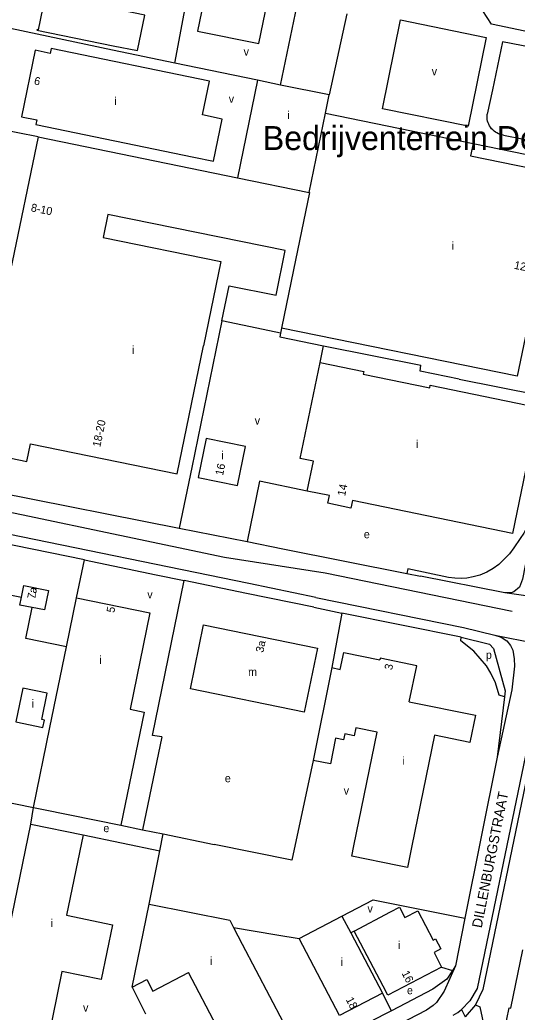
# Model space of a CAD drawing. Extents: x 157699 to 159683, y 381451 to 383293.
# Drawn here: x 158260 to 158508.3, y 381916.9 to 382412.9 of the extents above; entities that cross this region are included whole.
import ezdxf

# ---------------------------------------------------------------- set-up
doc = ezdxf.new("R2010")
doc.units = 0
for name, color, linetype in [('BLT_Basislijn', 7, 'Continuous'), ('BLT_Bebouwing', 7, 'Continuous'), ('BLT_Centroide', 7, 'Continuous'), ('BLT_Huisnummer', 7, 'Continuous'), ('BLT_Huisnummer_reeks', 7, 'Continuous'), ('BLT_Onderverdeling_panden', 7, 'Continuous'), ('BLT_Sport_parknaam', 7, 'Continuous'), ('BLT_Straatnaam', 7, 'Continuous'), ('BLT_Vlakafsluiter', 7, 'Continuous')]:
    doc.layers.add(name, color=color, linetype=linetype)

msp = doc.modelspace()

# ---------------------------------------------------------------- linework, layer by layer
at = {"layer": 'BLT_Basislijn'}
for p, q in [((158337.32, 382391.27), (158346.43, 382439.27)), ((158306.25, 382397.75), (158255.23, 382408.53)), ((158337.32, 382391.27), (158306.25, 382397.75)), ((158378.71, 382382.67), (158337.32, 382391.27)), ((158495.93, 382377.87), (158493.34, 382365.67)), ((158269.05, 382354.34), (158245.09, 382359.23)), ((158501.45, 382355.29), (158511.7, 382353.19)), ((158486.34, 382351.12), (158552.63, 382337.43)), ((158360.88, 382262.39), (158345.82, 382189.15)), ((158390.17, 382256.36), (158389.79, 382254.49)), ((158389.79, 382254.49), (158411.61, 382249.88)), ((158409.9, 382241.62), (158411.61, 382249.88)), ((158411.61, 382249.88), (158460.22, 382240.26)), ((158479.27, 382233.29), (158518.84, 382225.38)), ((158345.82, 382189.15), (158339.58, 382158.81)), ((158223.44, 382181.91), (158339.58, 382158.81)), ((158339.58, 382158.81), (158373.42, 382152.08)), ((158292.26, 382142.92), (158246.44, 382152.33)), ((158373.42, 382152.08), (158391.35, 382148.52)), ((158391.35, 382148.52), (158453.2, 382136.22)), ((158292.26, 382142.92), (158328.02, 382135.51)), ((158328.02, 382135.51), (158342.01, 382132.6)), ((158453.2, 382136.22), (158460.05, 382134.85)), ((158373.22, 382126.19), (158342.01, 382132.6)), ((158406.73, 382119.25), (158373.22, 382126.19)), ((158406.73, 382119.25), (158420.67, 382116.39)), ((158480.29, 382104.36), (158420.67, 382116.39)), ((158330.81, 382054.44), (158321.29, 382008.06)), ((158406.35, 382042.77), (158395.81, 381992.8)), ((158236.05, 382025.53), (158266.85, 382019.2)), ((158265.37, 382010.94), (158266.85, 382019.2)), ((158291.58, 382005.49), (158329.89, 381997.56)), ((158310.34, 382010.3), (158321.29, 382008.06)), ((158321.29, 382008.06), (158331.56, 382005.96)), ((158329.89, 381997.56), (158331.56, 382005.96)), ((158331.56, 382005.96), (158357.02, 382000.76)), ((158395.81, 381992.8), (158357.02, 382000.76)), ((158324.59, 381970.86), (158329.89, 381997.56)), ((158366.61, 381959.29), (158388.32, 381955.55)), ((158426.96, 381957.47), (158425.18, 381956.54)), ((158388.32, 381955.55), (158399.38, 381953.65)), ((158470.57, 381939.46), (158476, 381937.73)), ((158316.02, 381929.43), (158322.77, 381916.03)), ((158445.55, 381917.65), (158440.98, 381926.41)), ((158480.51, 381918.19), (158482.27, 381914.6))]:
    msp.add_line(p, q, dxfattribs=at)
for points in [[(158533.71, 382395.49), (158535.16, 382402.41), (158495.57, 382410.69), (158488.96, 382420.8), (158500.45, 382475.74)], [(158533.71, 382395.49), (158501.04, 382401.96), (158495.93, 382377.87)], [(158501.45, 382355.29), (158500.6, 382355.44), (158499.76, 382355.66), (158498.95, 382355.96), (158498.18, 382356.34), (158497.43, 382356.78), (158496.74, 382357.29), (158496.09, 382357.86), (158495.5, 382358.49), (158494.97, 382359.18), (158494.51, 382359.91), (158494.12, 382360.67), (158493.79, 382361.47), (158493.55, 382362.3), (158493.38, 382363.15), (158493.29, 382364.01), (158493.28, 382364.87), (158493.34, 382365.67)], [(158479.27, 382233.29), (158459.82, 382237.37), (158460.22, 382240.26)], [(158403.49, 382177.37), (158379.65, 382182.28), (158373.42, 382152.08)], [(158208.33, 382176.62), (158362.08, 382144.32), (158412.5, 382136.57), (158505.73, 382117.34)], [(158518.16, 382169.99), (158517.16, 382170.25), (158515.34, 382164.61), (158513.1, 382159.29), (158511.61, 382156.3), (158509.83, 382153.6), (158506.57, 382148.93), (158504.42, 382146.04), (158502, 382143.42), (158499.11, 382140.72), (158496.4, 382138.66), (158493.14, 382136.89), (158489.59, 382135.3), (158486.33, 382134.46), (158483.25, 382133.9), (158480.45, 382133.72), (158477.19, 382133.81), (158474.02, 382134.18), (158453.69, 382138.48), (158453.19, 382136.22)], [(158518.16, 382169.99), (158510.96, 382133.33), (158509.41, 382129.31), (158506.7, 382127.02), (158505.37, 382126.57), (158502.18, 382126.47)], [(158407.75, 382124.15), (158374.23, 382131.09), (158247.44, 382157.23)], [(158288.3, 382124.03), (158292.26, 382142.92)], [(158200.59, 382135.68), (158199.19, 382129.38), (158209.54, 382127.4), (158210.85, 382134.13), (158260.84, 382124.37)], [(158502.18, 382126.47), (158460.05, 382134.85)], [(158330.81, 382054.44), (158326.16, 382055.27), (158342.01, 382132.6)], [(158407.75, 382124.15), (158481.47, 382109.22), (158497.16, 382105.39)], [(158283.26, 382099.43), (158262.9, 382103.65), (158266.11, 382119.17)], [(158420.67, 382116.39), (158415.82, 382089.12)], [(158497.16, 382105.39), (158500.27, 382104.28), (158503.2, 382102.5), (158504.93, 382100.16), (158506.11, 382097.86)], [(158501.98, 382074.55), (158499.39, 382075.38), (158497.48, 382081.52), (158495.14, 382086.36), (158492.98, 382089.94), (158486.73, 382097.34), (158480.21, 382102.49), (158480.29, 382104.36)], [(158480.29, 382104.36), (158494.53, 382100.88), (158496.54, 382098.73), (158502.26, 382077.58), (158501.98, 382074.55)], [(158506.11, 382097.86), (158506.88, 382093.45), (158506.97, 382089.79), (158505.58, 382078.02), (158498.34, 382044.29)], [(158501.98, 382074.55), (158498.34, 382044.29), (158482.25, 381963.84)], [(158515.99, 382058.89), (158513.23, 382049.22), (158488.25, 381928.78)], [(158513.38, 382035.19), (158491.19, 381928.17), (158487.42, 381920.58)], [(158420.83, 381964.84), (158436.32, 381973.11), (158482.25, 381963.84)], [(158482.25, 381963.84), (158477.43, 381940.01)], [(158476, 381937.73), (158473.26, 381933.38), (158466.16, 381928.41), (158445.55, 381917.65)], [(158477.43, 381940.01), (158471.84, 381927.48), (158467.98, 381921.78), (158466.32, 381920.25), (158462.98, 381917.95), (158449.15, 381910.73)], [(158477.43, 381940.01), (158476, 381937.73)], [(158488.25, 381928.78), (158484.73, 381922.58), (158480.51, 381918.19)], [(158445.55, 381917.65), (158441.82, 381915.71), (158400.71, 381894.19)], [(158476.39, 381915.37), (158478.7, 381916.71), (158480.51, 381918.19)], [(158487.42, 381920.58), (158482.27, 381914.6)], [(158487.42, 381920.58), (158489.7, 381919.53), (158492.32, 381907.09), (158495.94, 381898.53), (158502.7, 381885.02), (158531.64, 381827.11)]]:
    msp.add_lwpolyline(points, dxfattribs=at)
msp.add_lwpolyline([(158449.97, 382412.84), (158492.88, 382404.08), (158483.81, 382359.67), (158440.98, 382368.42)], close=True, dxfattribs=at)
at = {"layer": 'BLT_Bebouwing'}
for p, q in [((158423.23, 382415.87), (158414.43, 382375.34)), ((158390.2, 382380.31), (158378.71, 382382.67)), ((158412.58, 382366.3), (158414.43, 382375.34)), ((158404.43, 382326.67), (158412.58, 382366.3)), ((158412.58, 382366.3), (158486.34, 382351.12)), ((158269.05, 382354.34), (158368.69, 382333.98)), ((158396.65, 382287.98), (158390.67, 382258.79)), ((158390.67, 382258.79), (158390.17, 382256.36)), ((158338.58, 382185.98), (158351.74, 382250)), ((158400.02, 382193.72), (158409.9, 382241.62)), ((158431.48, 382235.84), (158464.62, 382228.97)), ((158518.94, 382219.05), (158506, 382156.09)), ((158406.58, 382192.36), (158400.02, 382193.72)), ((158283.26, 382099.43), (158288.3, 382124.03)), ((158288.3, 382124.03), (158324.93, 382116.48)), ((158324.93, 382116.48), (158315.06, 382068.33)), ((158275, 382059.18), (158283.26, 382099.43)), ((158415.82, 382089.12), (158406.35, 382042.77)), ((158321.99, 382066.87), (158310.34, 382010.3)), ((158315.06, 382068.33), (158321.99, 382066.87)), ((158266.85, 382019.2), (158275, 382059.18)), ((158266.85, 382019.2), (158271.74, 382018.19)), ((158271.74, 382018.19), (158310.34, 382010.3)), ((158253.39, 381952.43), (158265.37, 382010.94)), ((158265.37, 382010.94), (158291.58, 382005.49)), ((158291.58, 382005.49), (158283.22, 381965.39)), ((158399.38, 381953.65), (158420.83, 381964.84)), ((158366.61, 381959.29), (158371.01, 381950.82)), ((158505.15, 381918.91), (158511.11, 381948.09)), ((158501.99, 381907.7), (158504.27, 381919.1))]:
    msp.add_line(p, q, dxfattribs=at)
for points in [[(158379.37, 382401), (158398.01, 382491.76)], [(158368.21, 382457.15), (158359.39, 382458.96), (158348.75, 382407.31), (158379.37, 382401)], [(158277.24, 382443.21), (158272.08, 382418.25), (158271.28, 382418.42), (158269.12, 382407.98)], [(158306.63, 382399.96), (158318.68, 382397.49), (158322.32, 382415.25), (158310.27, 382417.72), (158313.96, 382435.7)], [(158390.2, 382380.31), (158399.27, 382424.37), (158389.72, 382426.3)], [(158269.12, 382407.98), (158268.57, 382408.09), (158268.49, 382407.77), (158306.63, 382399.96)], [(158267.57, 382397.67), (158260.72, 382364.43), (158268.37, 382362.85), (158267.88, 382360.5), (158346.81, 382344.21), (158356.6, 382342.19), (158360.96, 382363.32), (158351.17, 382365.34), (158354.65, 382382.22)], [(158275.68, 382398.52), (158275.17, 382396.12), (158267.57, 382397.67)], [(158354.65, 382382.22), (158275.68, 382398.52)], [(158378.71, 382382.67), (158368.69, 382333.98)], [(158269.05, 382354.34), (158255.36, 382287.79), (158251.26, 382288.64), (158246.7, 382266.18), (158250.79, 382265.4), (158242.04, 382222.93), (158232.57, 382224.87), (158227.38, 382199.6), (158263.48, 382192.17), (158265.31, 382201.04), (158338.58, 382185.98)], [(158486.34, 382351.12), (158485.06, 382344.86), (158531.46, 382335.37), (158529.01, 382323.57), (158526.65, 382324.06), (158525.58, 382318.93), (158527.95, 382318.43), (158520.28, 382281.49), (158518.09, 382281.94), (158508.38, 382234.73), (158390.67, 382258.79)], [(158404.43, 382326.67), (158404.58, 382326.64), (158396.65, 382287.98)], [(158360.88, 382262.39), (158364.47, 382280.01), (158387.91, 382275.23), (158392.42, 382297.55), (158303.93, 382315.64), (158301.55, 382304.17), (158360.36, 382292.15), (158351.74, 382250)], [(158381.47, 382258.15), (158360.88, 382262.39)], [(158390.17, 382256.36), (158381.47, 382258.15)], [(158409.9, 382241.62), (158431.74, 382237.11), (158431.48, 382235.84)], [(158464.62, 382228.97), (158464.88, 382230.25), (158518.94, 382219.05)], [(158403.49, 382177.37), (158406.58, 382192.36)], [(158425.28, 382168.85), (158413.72, 382171.24), (158414.52, 382175.09), (158403.49, 382177.37)], [(158506, 382156.09), (158426.08, 382172.73), (158425.28, 382168.85)], [(158260.84, 382124.37), (158262.02, 382130.14), (158274.19, 382127.65)], [(158274.19, 382127.65), (158272.2, 382117.92), (158266.11, 382119.17)], [(158266.11, 382119.17), (158260.03, 382120.41), (158260.84, 382124.37)], [(158415.82, 382089.12), (158419.99, 382088.26), (158421.73, 382096.74), (158439.74, 382093.05)], [(158454.45, 382072.08), (158458.12, 382090.06), (158439.89, 382093.79), (158439.74, 382093.05)], [(158261.47, 382078.79), (158258.03, 382062.03), (158271.5, 382059.27)], [(158273.61, 382076.3), (158261.47, 382078.79)], [(158271.5, 382059.27), (158272.23, 382062.84), (158270.91, 382063.11), (158273.61, 382076.3)], [(158454.45, 382072.08), (158487.5, 382065.32), (158484.71, 382051.67), (158467.01, 382055.29), (158455.7, 381999.99), (158453.46, 381989.21), (158448.56, 381990.22), (158425.77, 381994.89), (158426.81, 382000), (158438.43, 382056.84), (158427.66, 382059.05), (158426.83, 382055.02), (158422.19, 382055.97), (158421.59, 382053.03), (158417.65, 382053.83), (158415.03, 382041), (158406.35, 382042.77)], [(158316.02, 381929.43), (158324.59, 381970.86)], [(158324.59, 381970.86), (158364.74, 381962.89), (158366.61, 381959.29)], [(158426.96, 381957.47), (158445.13, 381967), (158449.55, 381969.32), (158452.27, 381964.15), (158458.66, 381967.51), (158466.32, 381952.91), (158467.51, 381953.53), (158470.12, 381948.52), (158466.82, 381946.72), (158470.57, 381939.46)], [(158283.22, 381965.39), (158306.23, 381960.62), (158300.56, 381933.23), (158280.97, 381937.29)], [(158420.83, 381964.84), (158425.18, 381956.54)], [(158425.18, 381956.54), (158440.98, 381926.41)], [(158443.79, 381925.41), (158441.47, 381929.84), (158426.96, 381957.47)], [(158440.98, 381926.41), (158419.52, 381915.24), (158399.38, 381953.65)], [(158371.01, 381950.82), (158391.45, 381911.89), (158393.78, 381907.46)], [(158280.97, 381937.29), (158271.56, 381891.25), (158276.45, 381890.19), (158274.36, 381879.91), (158264.45, 381881.89), (158264, 381879.82)], [(158316.02, 381929.43), (158323.29, 381933.25), (158326.37, 381927.38), (158344.12, 381936.7)], [(158363.82, 381883.48), (158361.5, 381887.9), (158351.85, 381906.33), (158358.3, 381909.71), (158344.12, 381936.7)], [(158470.57, 381939.46), (158443.79, 381925.41)], [(158504.27, 381919.1), (158505.15, 381918.91)]]:
    msp.add_lwpolyline(points, dxfattribs=at)
for points in [[(158353.05, 382203.68), (158349.08, 382184.18), (158368.57, 382180.19), (158372.56, 382199.69)], [(158351.71, 382110.43), (158408.52, 382098.79), (158401.98, 382066.86), (158345.17, 382078.49)]]:
    msp.add_lwpolyline(points, close=True, dxfattribs=at)
at = {"layer": 'BLT_Onderverdeling_panden'}
for p, q in [((158414.43, 382375.34), (158390.2, 382380.31)), ((158368.69, 382333.98), (158404.43, 382326.67))]:
    msp.add_line(p, q, dxfattribs=at)
at = {"layer": 'BLT_Vlakafsluiter'}
for p, q in [((158521.66, 382123.63), (158502.18, 382126.47)), ((158497.16, 382105.39), (158517.24, 382101.36))]:
    msp.add_line(p, q, dxfattribs=at)

# ---------------------------------------------------------------- texts
at = {"layer": 'BLT_Centroide'}
for s, p in [('v', (158371.7, 382395)), ('v', (158465.63, 382385.2)), ('i', (158307.07, 382370.34)), ('v', (158364.28, 382371.42)), ('i', (158393.47, 382363.29)), ('i', (158475.65, 382298.03)), ('i', (158315.98, 382245.92)), ('v', (158377.25, 382210.61)), ('i', (158457.81, 382198.91)), ('i', (158360.6, 382193.28)), ('e', (158431.72, 382153.79)), ('i', (158267.11, 382124.03)), ('v', (158323.61, 382123.72)), ('i', (158299.64, 382090.97)), ('p', (158492.68, 382093.51)), ('m', (158373.94, 382085.01)), ('i', (158265.81, 382069.17)), ('i', (158451.02, 382040.62)), ('e', (158362.32, 382031.83)), ('v', (158421.67, 382025.64)), ('e', (158301.66, 382006.88)), ('v', (158433.55, 381966.66)), ('i', (158275.36, 381959.48)), ('i', (158448.77, 381948.47)), ('i', (158354.91, 381940.52)), ('i', (158420.17, 381940.05)), ('e', (158453.28, 381925.87)), ('v', (158291.53, 381917.18))]:
    msp.add_text(s, height=4, dxfattribs=at).set_placement(p)
at = {"layer": 'BLT_Huisnummer'}
for s, rotation, p in [('6', 348.3395, (158266.8, 382380.63)), ('12b', 348.4264, (158506.53, 382288.53)), ('16', 78.3408, (158361.4, 382184.88)), ('14', 78.3408, (158422.38, 382174.61)), ('7a', 78.4332, (158267.5, 382123.1)), ('5', 78.5336, (158307.07, 382116.27)), ('3a', 78.4422, (158381.55, 382096.41)), ('3', 78.4422, (158445.84, 382087.66)), ('16', 297.6891, (158450.48, 381936.39)), ('18', 297.6699, (158422.58, 381923.23))]:
    msp.add_text(s, height=4, rotation=rotation, dxfattribs=at).set_placement(p)
at = {"layer": 'BLT_Huisnummer_reeks'}
for s, rotation, p in [('8-10', 348.4509, (158265.23, 382317.27)), ('18-20', 78.3811, (158300.12, 382199.11))]:
    msp.add_text(s, height=4, rotation=rotation, dxfattribs=at).set_placement(p)
at = {"layer": 'BLT_Sport_parknaam'}
msp.add_text('Bedrijventerrein De Hurk', height=12, dxfattribs=at).set_placement((158381.28, 382347.82))
at = {"layer": 'BLT_Straatnaam'}
msp.add_text('DILLENBURGSTRAAT', height=5, rotation=78.8684, dxfattribs=at).set_placement((158490.57, 381958.72))

doc.saveas('drawing.dxf')
